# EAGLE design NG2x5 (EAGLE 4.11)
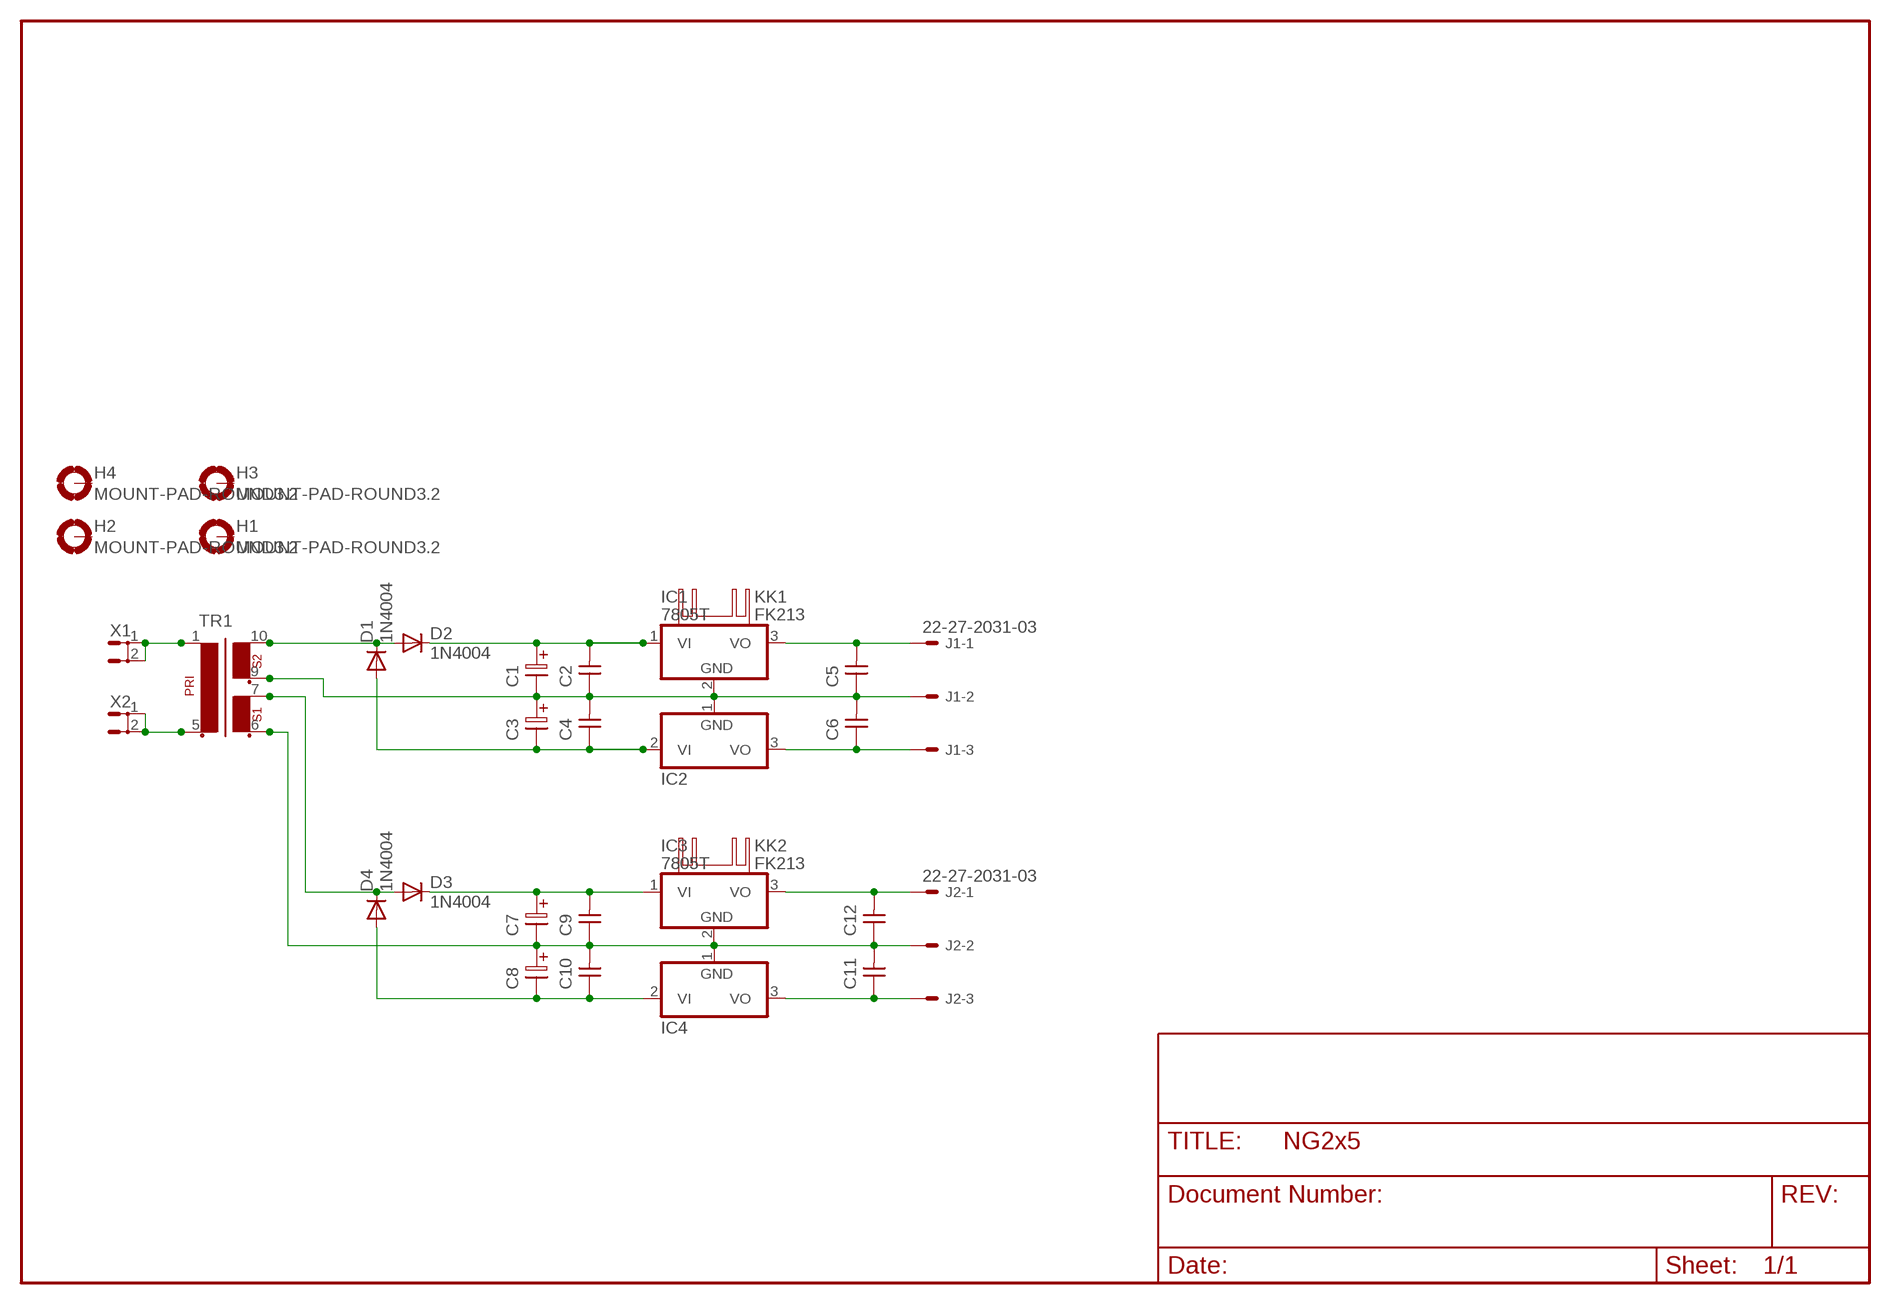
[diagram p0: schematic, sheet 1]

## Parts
C1  ELC-5  [ES-5]
C2  CAPNP-2,5  [C-2,5]
C3  ELC-2,5  [ES-2,5]
C4  CAPNP-2,5  [C-2,5]
C5  CAPNP-2,5  [C-2,5]
C6  CAPNP-2,5  [C-2,5]
C7  ELC-5  [ES-5]
C8  ELC-2,5  [ES-2,5]
C9  CAPNP-2,5  [C-2,5]
C10  CAPNP-2,5  [C-2,5]
C11  CAPNP-2,5  [C-2,5]
C12  CAPNP-2,5  [C-2,5]
D1  1N4004  [DO41-10]
D2  1N4004  [DO41-10]
D3  1N4004  [DO41-10]
D4  1N4004  [DO41-10]
H1  MOUNT-PAD-ROUND3.2  [3,2-PAD]
H2  MOUNT-PAD-ROUND3.2  [3,2-PAD]
H3  MOUNT-PAD-ROUND3.2  [3,2-PAD]
H4  MOUNT-PAD-ROUND3.2  [3,2-PAD]
IC1  7805T  [TO220H]
IC2  7905L  [TO92]
IC3  7805T  [TO220H]
IC4  7905L  [TO92]
J1  22-27-2031-03  [6410-03]
J2  22-27-2031-03  [6410-03]
KK1  FK213  [FK213]
KK2  FK213  [FK213]
TR1  EI38-2  [EI38-2]
X1  ST6,3  [ST6,3]
X2  ST6,3  [ST6,3]

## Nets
GND1: C1.2 C2.1 C3.1 C4.2 C5.1 C6.2 IC1.2(GND) IC2.1(GND) J1.2 TR1.9
GND2: C7.2 C8.1 C9.1 C10.2 C11.2 C12.1 IC3.2(GND) IC4.1(GND) J2.2 TR1.6
N$1: D1.C D2.A TR1.10
N$2: C1.1 C2.2 D2.C IC1.1(VI)
N$4: C3.2 C4.1 D1.A IC2.2(VI)
N$6: C6.1 IC2.3(VO) J1.3
N$7: C5.2 IC1.3(VO) J1.1
N$11: D3.A D4.C TR1.7
N$12: C7.1 C9.2 D3.C IC3.1(VI)
N$13: C8.2 C10.1 D4.A IC4.2(VI)
N$15: C12.2 IC3.3(VO) J2.1
N$17: TR1.5 X2.1 X2.2
N$18: TR1.1 X1.1 X1.2
VC: C11.1 IC4.3(VO) J2.3
Unconnected: H1.B3,2(MOUNT) H2.B3,2(MOUNT) H3.B3,2(MOUNT) H4.B3,2(MOUNT)

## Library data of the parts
C1 C7 = discrete:ELC-5
C2 C4-C6 C9-C12 = discrete:CAPNP-2,5
C3 C8 = discrete:ELC-2,5
D1-D4 = diode:1N4004: DIODE
H1-H4 = holes:MOUNT-PAD-ROUND: MOUNTING PAD, round
IC1 IC3 = linear:78*: Positive VOLTAGE REGULATOR
IC2 IC4 = linear:79*: Negative VOLTAGE REGULATOR
J1 J2 = EP_molex_6410_7395:22-?-03: CONNECTOR wire to board 2.54 mm (.1 inch) pitch header
KK1 KK2 = heatsink:FK213: HEATSINK
TR1 = trafo:EI38-2: TRANSFORMER 1 primary winding, 2 secondary windings ERA
X1 X2 = con-rib:ST6,3: RIBBON CABLE CONNECTOR

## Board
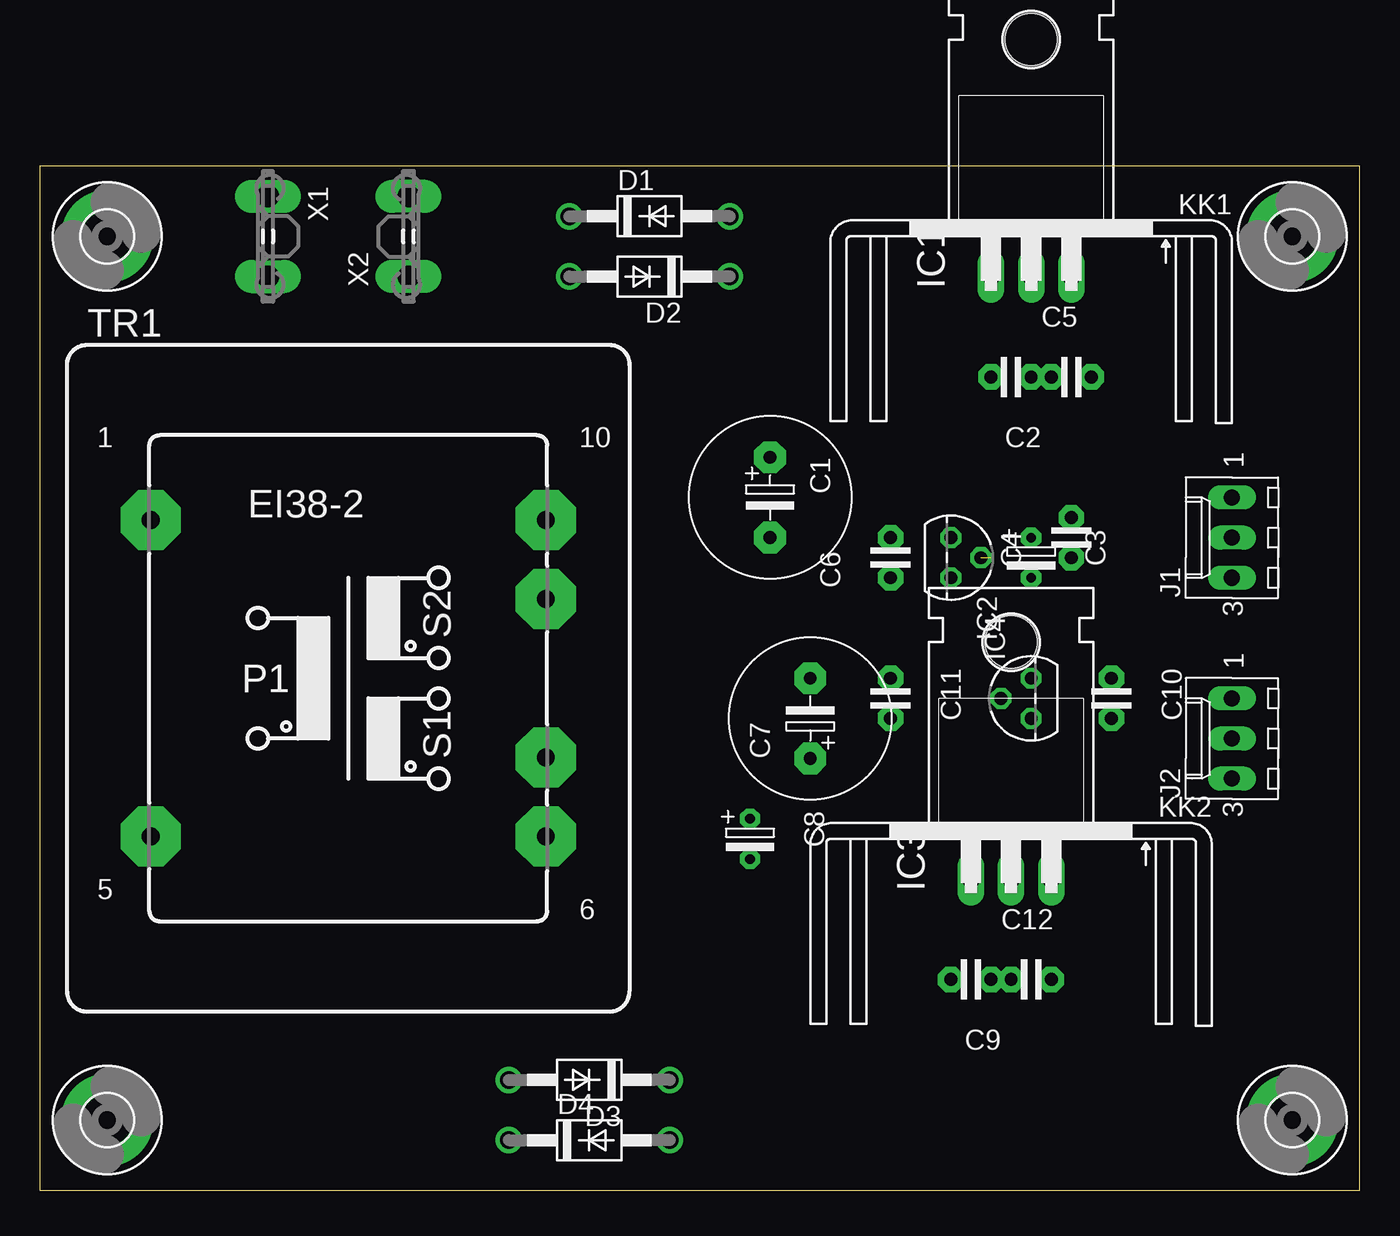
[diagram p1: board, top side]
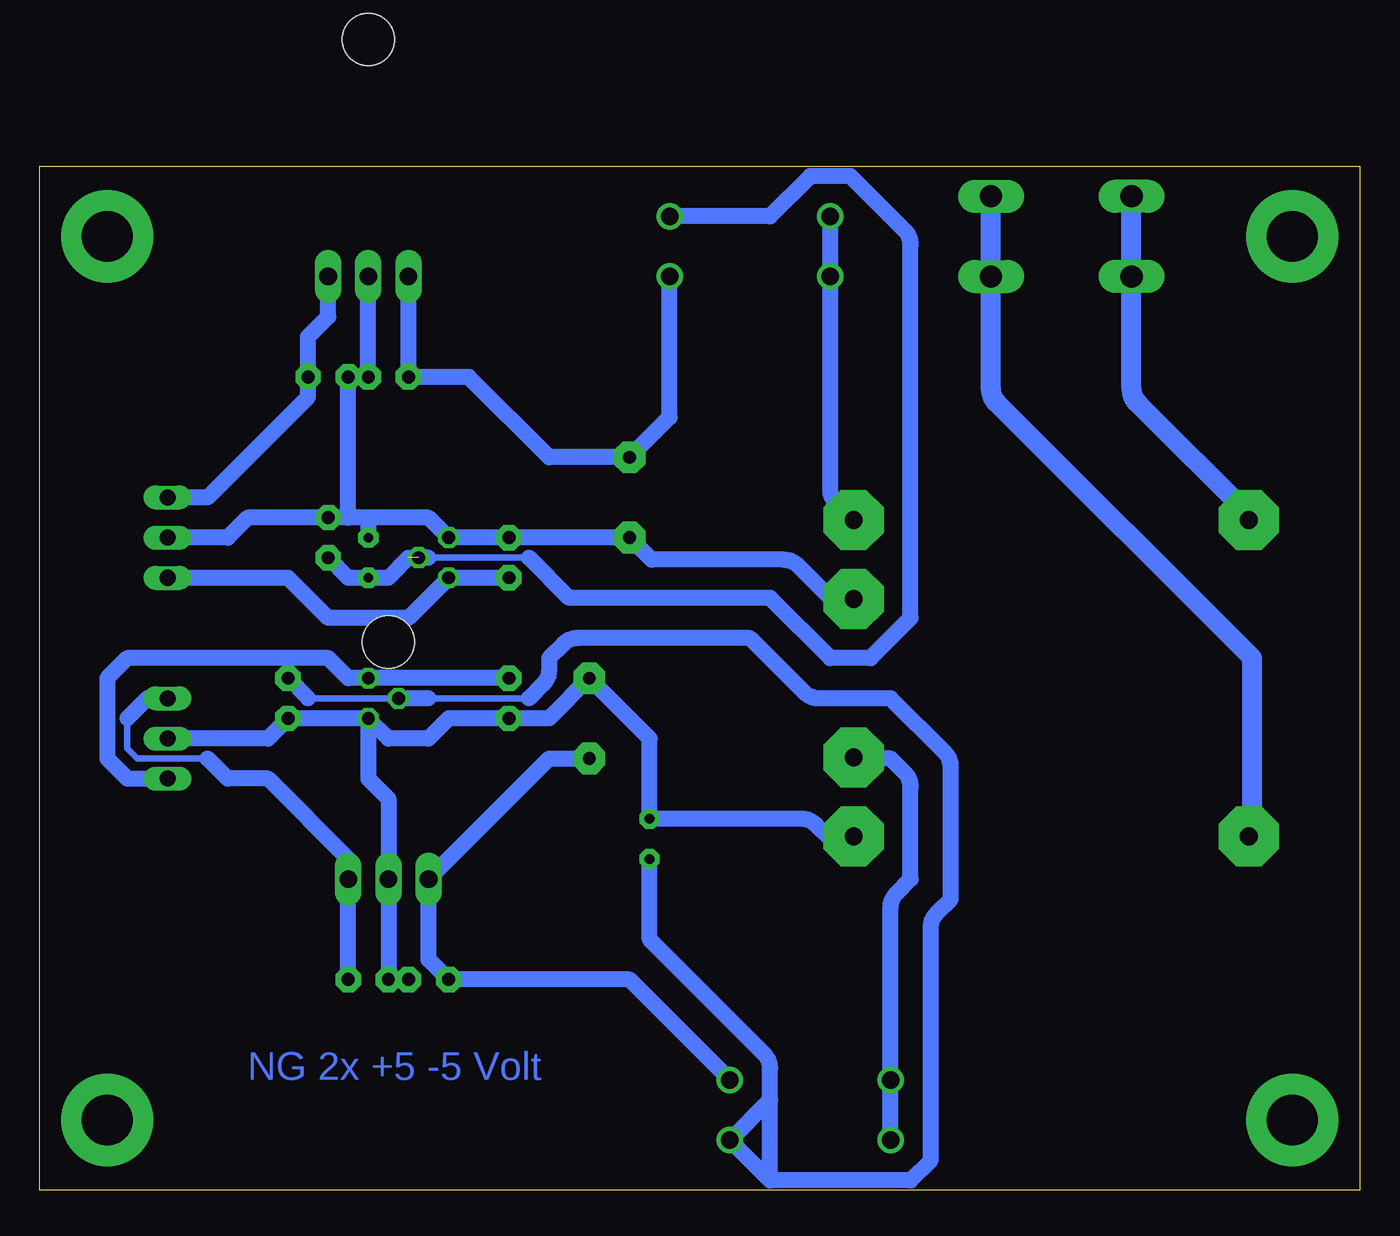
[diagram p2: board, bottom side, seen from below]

Size 83.49 x 64.76 mm. Coordinates in mm from the lower left corner, seen from the top.
Outline: 0,0 83.49,0 83.49,64.76 0,64.76 0,0
Copper layers (1*16): Top 0.035mm / dielectric 1.5mm / Bottom 0.035mm
Design rules "default": minimum track width 10mil, minimum drill 24mil, track to track 25mil, track to pad 25mil, pad to pad 8mil, via to via 8mil, smd to smd 8mil, copper to edge 40mil, drill to drill 8mil, minimum pad ring 10mil, minimum via ring 8mil, stop-mask expansion 4mil, vias tented up to drill 0mil, thermal gap 10mil

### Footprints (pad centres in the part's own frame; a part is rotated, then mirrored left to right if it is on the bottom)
ES-5 = drill 0.813 pad 2.007 octagon: 1 -2.54,0; 2 2.54,0
C-2,5 = drill 0.813 pad 1.6 octagon: 1 -1.27,0; 2 1.27,0
ES-2,5 = drill 0.61 pad 1.27 octagon: 1 -1.27,0; 2 1.27,0
DO41-10 = drill 1.118 round: A 5.08,0; C -5.08,0
3,2-PAD = drill 3.2 pad 5.842 round: B3,2 0,0
TO220H = drill 1.118 long: 1 -2.54,-10.16; 2 0,-10.16; 3 2.54,-10.16 | hole 3.302: 0,4.826
TO92 = drill 0.813 octagon: 1 -1.27,0; 2 0,1.905; 3 1.27,0
6410-03 = drill 1.016 long: 1 2.54,0; 2 0,0; 3 -2.54,0
EI38-2 = drill 1.118 pad 3.81 octagon: 1 -12.497,10.008; 5 -12.497,-10.008; 6 12.497,-10.008; 7 12.497,-5.004; 9 12.497,5.004; 10 12.497,10.008
ST6,3 = drill 1.397 long: 1 -2.54,0; 2 2.54,0

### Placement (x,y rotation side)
C1  46.19,43.81 270 top
C2  61.43,51.43 180 top
C3  62.7,40 270 top
C4  65.24,41.27 90 top
C5  65.24,51.43 0 top
C6  53.81,40 90 top
C7  48.73,29.84 90 top
C8  44.92,22.22 270 top
C9  58.89,13.33 180 top
C10  67.78,31.11 270 top
C11  53.81,31.11 270 top
C12  62.7,13.33 0 top
D1  38.57,61.59 0 top
D2  38.57,57.78 180 top
D3  34.76,6.98 180 top
D4  34.76,3.17 0 top
H1  4.28,60.32 0 top
H2  79.21,60.32 0 top
H3  79.21,4.44 0 top
H4  4.28,4.44 0 top
IC1  62.7,67.94 0 top
IC2  57.62,40 270 top
IC3  61.43,29.84 0 top
IC4  62.7,31.11 90 top
J1  75.4,41.27 90 top
J2  75.4,28.57 90 top
KK1  62.7,60.32 180 top
KK2  61.43,22.22 180 top
TR1  19.52,32.38 0 top
X1  14.44,60.32 270 top
X2  23.33,60.32 90 top

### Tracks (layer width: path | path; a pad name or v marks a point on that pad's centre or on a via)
GND1
  Bottom 1.016: J1.2 71.59,41.27 70.32,42.54 C4.2 63.97,42.54 | IC1.2 C2.1 C5.1 63.97,42.54 | 62.7,42.54 58.89,42.54 IC2.1 C6.2 C1.2 44.79,39.87 36.43,39.87 arc45 35.53,39.5 33.49,37.46 32.22,37.46 arc-45 32.04,37.38 TR1.9 | 62.7,42.54 63.97,42.54 | 62.7,42.54 C3.1
GND2
  Bottom 1.016: IC4.1 61.43,28.57 58.89,28.57 57.62,29.84 C11.2 51.27,29.84 C7.2 44.92,28.57 C8.1 35.29,23.49 arc45 34.39,23.12 33.49,22.22 32.22,22.22 32.1,22.34 | IC4.1 62.7,26.03 61.43,24.76 IC3.2 C12.1 C9.1 | IC4.1 C10.2 69.05,28.57 J2.2 | 32.1,22.34 arc45 TR1.6 arc-45 32.1,22.34
N$1
  Bottom 1.016: D1.C D2.A 33.49,44.34 arc-45 33.12,43.44 32.1,42.42 arc-45 TR1.10
N$2
  Bottom 1.016: D2.C 43.65,48.89 C1.1 51.27,46.35 56.35,51.43 C2.2 IC1.1
N$4  (1 unrouted)
  Bottom 0.406: 52.54,40 58.89,40
  Bottom 1.016: 60.16,40 61.43,38.73 C3.2 63.97,38.73 C4.1 | 58.89,40 IC2.2 | 52.54,40 50,37.46 37.3,37.46 33.49,33.65 30.95,33.65 28.41,36.19 28.41,59.79 arc-45 28.78,60.69 32.22,64.13 34.76,64.13 37.3,61.59 D1.A
N$6
  Bottom 1.016: C6.1 IC2.3 60.16,36.19 65.24,36.19 67.78,38.73 J1.3
N$7
  Bottom 1.016: IC1.3 65.24,55.24 66.51,53.97 C5.2 66.51,50.16 72.86,43.81 J1.1
N$11
  Bottom 1.016: D4.C D3.A 29.68,17.88 arc45 29.31,18.78 28.41,19.68 28.41,25.5 arc-45 28.78,26.4 29.68,27.3 32.22,27.3 arc45 32.04,27.38 TR1.7
N$12
  Bottom 1.016: D3.C 46.19,13.33 C9.2 58.89,14.6 IC3.1 51.27,27.3 C7.1
N$13
  Bottom 0.406: IC4.2 66.51,31.11 | 52.54,31.11 58.89,31.11
  Bottom 1.016: 66.51,31.11 C10.1 | 58.89,31.11 IC4.2 | 37.3,5.71 D4.A 37.3,0.63 | 37.3,5.71 37.3,7.72 arc-45 37.67,8.62 44.92,15.87 C8.2 | 52.54,31.11 51.64,32.01 arc-45 51.27,32.91 51.27,33.65 50.37,34.55 arc45 49.47,34.92 38.57,34.92 35.13,31.48 arc-45 34.23,31.11 29.68,31.11 26.24,27.67 arc45 25.87,26.77 25.87,18.41 26.77,17.51 arc-45 27.14,16.61 27.14,1.9 28.41,0.63 37.3,0.63 | 37.3,0.63 37.3,5.71
N$15
  Bottom 0.406: 72.86,27.3 77.3,27.3 77.94,27.94 77.94,29.84
  Bottom 1.016: C12.2 IC3.3 63.97,20.95 69.05,26.03 71.59,26.03 72.86,27.3 | 77.94,29.84 76.67,31.11 J2.1
N$17
  Bottom 1.27: X2.2 X2.1 23.33,50.69 arc-45 22.96,49.79 6.82,33.65 6.82,22.22 6.94,22.34 arc-45 TR1.5
N$18
  Bottom 1.27: X1.1 X1.2 14.44,50.69 arc-45 14.07,49.79 6.82,42.54 6.94,42.42 arc45 TR1.1
VC
  Bottom 1.016: C11.1 IC4.3 63.97,32.38 65.24,33.65 77.94,33.65 79.21,32.38 79.21,27.3 77.94,26.03 J2.3

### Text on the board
Bottom: NG 2x +5 -5 Volt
